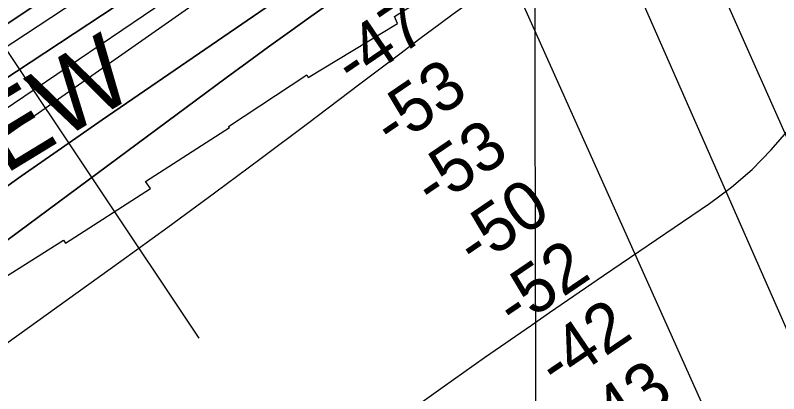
# Model space of a CAD drawing. Extents: x 3324104 to 3361979, y 612876 to 638273.
# Drawn here: x 3353821 to 3354870, y 621139 to 621658 of the extents above; entities that cross this region are included whole.
import ezdxf

# ---------------------------------------------------------------- set-up
doc = ezdxf.new("R2010")
doc.units = 0
for name, color, linetype in [('V-GRID-MAJR', 7, 'Continuous'), ('V-RIVR-EDGE', 7, 'Continuous'), ('V-RIVR-RANG', 7, 'Continuous'), ('V-RRAP-RVMT', 7, 'Continuous'), ('V-RRAP-RVMT-IDEN', 7, 'Continuous'), ('V-TOPO-DPTH', 7, 'Continuous'), ('V-TOPO-MAJR', 7, 'Continuous'), ('V-TOPO-MINR', 7, 'Continuous'), ('V-TOPO-WATR', 7, 'Continuous'), ('V-UTIL-LINE', 7, 'Continuous')]:
    doc.layers.add(name, color=color, linetype=linetype)

msp = doc.modelspace()

# ---------------------------------------------------------------- linework, layer by layer
at = {"layer": 'V-GRID-MAJR'}
msp.add_spline([(3354542.6, 618302.9), (3354530.3, 624362.2), (3354517.9, 630423.5), (3354505.6, 636484.8), (3354505.6, 636486.7)], degree=3, dxfattribs=at)
at = {"layer": 'V-RIVR-EDGE'}
msp.add_spline([(3356052, 622889.6), (3356029.2, 622881.4), (3356012.5, 622875.7), (3355994.6, 622867.2), (3355977.5, 622859.1), (3355958.5, 622851), (3355948.4, 622843.2), (3355934, 622834.7), (3355904.1, 622817.8), (3355878.1, 622802.3), (3355856.7, 622790.3), (3355830, 622776.4), (3355805.1, 622765.6), (3355764.7, 622744.8), (3355744.1, 622733.6), (3355694.1, 622710.9), (3355668.4, 622698.1), (3355641.6, 622685), (3355605.1, 622669.2), (3355569.4, 622657.3), (3355539.2, 622646.5), (3355510.8, 622636.8), (3355482.1, 622628.4), (3355461.9, 622623), (3355442.5, 622614.1), (3355422.7, 622607.2), (3355409.5, 622603.4), (3355389, 622597.6), (3355371.9, 622589.5), (3355349, 622581), (3355297.7, 622547), (3355260, 622525.8), (3355211.1, 622494.5), (3355190.1, 622484.5), (3355184.7, 622482.9), (3355179.3, 622477.9), (3355174.2, 622475.6), (3355160.6, 622471), (3355143.5, 622463.6), (3355133.1, 622457.1), (3355125.7, 622450.5), (3355113.2, 622443.9), (3355096.9, 622433.1), (3355081, 622426.9), (3355064.3, 622419.2), (3355057, 622418.9), (3355048.8, 622414.6), (3355041.8, 622406.9), (3355036.8, 622406.5), (3355031.3, 622405.7), (3355027.1, 622404.2), (3355017.3, 622396.1), (3355010.7, 622394.9), (3355001.4, 622388.4), (3354988.6, 622379.1), (3354972.3, 622369.4), (3354947.4, 622356.3), (3354937.7, 622351.7), (3354926.1, 622343.6), (3354903.2, 622326.6), (3354891.1, 622318.1), (3354883.3, 622307.2), (3354879.4, 622304.1), (3354875.2, 622302.6), (3354867.8, 622299.1), (3354853, 622288.3), (3354842.5, 622279), (3354826.6, 622267.4), (3354807.2, 622259.7), (3354793.2, 622255.5), (3354765.7, 622249.7), (3354748.6, 622245.5), (3354734.6, 622239.3), (3354712.1, 622227.4), (3354697.7, 622218.9), (3354685.3, 622210), (3354640.6, 622184.5), (3354622, 622176), (3354616.2, 622175.2), (3354603.4, 622167.5), (3354578.9, 622157.1), (3354554.5, 622147.5), (3354537.4, 622142.9), (3354530.8, 622137.8), (3354500.1, 622122.8), (3354463.6, 622102.3), (3354417.8, 622078.8), (3354386.3, 622060.6), (3354340.1, 622032.4), (3354321.1, 622021.2), (3354285, 621998.8), (3354257, 621982.2), (3354217, 621958.7), (3354194.1, 621942.8), (3354177, 621931.6), (3354157.6, 621922), (3354141.6, 621910.4), (3354135.4, 621904.2), (3354130.4, 621897.6), (3354120.7, 621891.1), (3354104, 621882.9), (3354075.6, 621856.6), (3354044.9, 621835.4), (3354013, 621812.2), (3353971.5, 621781.7), (3353947.8, 621763.5), (3353941.2, 621763.5), (3353935.4, 621762.8), (3353929.5, 621760.1), (3353924.9, 621756.6), (3353920.6, 621751.5), (3353917.1, 621742.6), (3353910.5, 621741.5), (3353904.7, 621738.4), (3353893.8, 621731.1), (3353879.8, 621721.4), (3353866.2, 621708.6), (3353854.9, 621697.4), (3353843.3, 621687.8), (3353839.8, 621688.5), (3353831.2, 621686.2), (3353823.1, 621681.2), (3353818, 621677.3), (3353800.9, 621666.1), (3353790.8, 621663.1), (3353781.9, 621654.9), (3353777.6, 621651.8), (3353776.1, 621648.8), (3353775.7, 621643.7), (3353772.2, 621641), (3353755.9, 621632.1), (3353735.7, 621622.1), (3353718.6, 621608.2), (3353704.2, 621600.5), (3353694.1, 621596.6), (3353683.6, 621592.4), (3353671.2, 621584.2), (3353642.1, 621563), (3353599, 621534), (3353578.4, 621522.4), (3353556.2, 621507.7), (3353547.7, 621502), (3353525.9, 621489.2), (3353513.1, 621481.1), (3353497.2, 621468.3), (3353477, 621450.9), (3353453.3, 621436.6), (3353435.8, 621424.7), (3353404.7, 621401.1), (3353378.3, 621380.2), (3353361.6, 621368.6), (3353339.5, 621355.1), (3353319.6, 621342.4), (3353299.5, 621330), (3353283.5, 621324.6), (3353273, 621317.6), (3353254.8, 621296), (3353236.9, 621275.5), (3353219.4, 621258.8), (3353195.7, 621241.4), (3353168.5, 621221.3), (3353137.8, 621201.6), (3353112.2, 621185), (3353065.6, 621151.8), (3353022, 621122.8), (3352993.3, 621100.4), (3352956, 621073.3), (3352907, 621037.8), (3352853.8, 620991.8), (3352787.8, 620942.3), (3352749.7, 620913.3), (3352736.9, 620900.9), (3352733.3, 620892.8), (3352728.7, 620886.6), (3352719, 620881.2), (3352691.8, 620864.6), (3352660.3, 620841.8), (3352640.5, 620828.3), (3352623.4, 620811.2), (3352605.1, 620792.3), (3352593.5, 620783), (3352582.6, 620778.8), (3352566.3, 620771.4), (3352548, 620764.5), (3352522.4, 620751), (3352494.5, 620735.5), (3352482.4, 620727), (3352479.3, 620723.2), (3352477, 620717.4), (3352470.7, 620711.9), (3352456, 620707.3), (3352443.2, 620700.4), (3352419.1, 620685.7), (3352392.3, 620669.1), (3352362.8, 620650.9), (3352339.1, 620634.3), (3352315.4, 620615.4), (3352284.7, 620590.6), (3352258.7, 620571.3), (3352228.7, 620550.1), (3352193.4, 620527.6), (3352156.9, 620504.9), (3352131.6, 620487.5), (3352094, 620462.4), (3352049.3, 620433), (3351990.2, 620391.3), (3351936.6, 620357.3), (3351851.5, 620293.9), (3351833.3, 620281.5), (3351817, 620273.8), (3351794.1, 620257.9), (3351767.7, 620241), (3351719.9, 620206.2), (3351680.6, 620177.6), (3351657.3, 620160.6), (3351637.1, 620145.9), (3351623.1, 620135.4), (3351603.3, 620124.2), (3351588.6, 620120), (3351567.2, 620109.6), (3351552.1, 620103.4), (3351538.1, 620096.5), (3351523.7, 620086.4), (3351510.9, 620076.4), (3351503.5, 620069.8), (3351495.3, 620057.4), (3351486, 620042.3), (3351479.4, 620032.6), (3351469.7, 620022.6), (3351448.3, 620006.3), (3351431.6, 619994.8), (3351404.8, 619973.9), (3351378, 619951.8), (3351358.9, 619936.4), (3351332.1, 619915.5), (3351306.1, 619892.3), (3351274.6, 619858.2), (3351238.8, 619826.9), (3351215.1, 619805.7), (3351171.6, 619767.8), (3351145.5, 619739.5), (3351124.6, 619722.1), (3351105.9, 619707.8), (3351089.6, 619697), (3351079.5, 619691.2), (3351074, 619683.5), (3351058.1, 619666.4), (3351043.3, 619655.2), (3351015.4, 619634), (3350999, 619623.1), (3350992.1, 619617.3), (3350979.2, 619606.1), (3350966, 619594.5), (3350951.2, 619582.2), (3350935.7, 619567.8), (3350923.3, 619555.1), (3350910, 619544.3), (3350888.3, 619528), (3350846.7, 619504.1), (3350821.5, 619490.2), (3350811.4, 619483.6), (3350806, 619480.5), (3350800.9, 619473.2), (3350797.4, 619473.2), (3350793.9, 619474.3), (3350788.9, 619473.6), (3350786.9, 619472), (3350785.4, 619467.4), (3350785.4, 619462.7), (3350779.5, 619456.2), (3350765.9, 619445.7), (3350746.1, 619428.7), (3350722.4, 619409), (3350716.2, 619407.1), (3350713.1, 619404), (3350711.1, 619397), (3350708.8, 619391.6), (3350704.5, 619391.6), (3350693.3, 619385.8), (3350686.7, 619379.6), (3350679.6, 619368.4), (3350661.4, 619354.5), (3350648.6, 619344.4), (3350645.5, 619344.8), (3350638.5, 619339.4), (3350623.3, 619330.5), (3350616.3, 619326.3), (3350602.3, 619317.4), (3350598.8, 619308.8), (3350582.9, 619299.2), (3350553.8, 619276), (3350526.2, 619255.5), (3350493.5, 619231.9), (3350474.9, 619219.6), (3350474.5, 619213.8), (3350470.2, 619207.2), (3350459, 619202.5), (3350446.1, 619194), (3350441.1, 619189.8), (3350438.8, 619186.3), (3350434.5, 619180.9), (3350414.7, 619167.8), (3350401.5, 619159.3), (3350384.8, 619146.9), (3350369.6, 619133.7), (3350356.4, 619125.2), (3350350.9, 619119), (3350347.4, 619109.4), (3350338.1, 619097.8), (3350324.9, 619083.8), (3350308.6, 619069.9), (3350300.4, 619062.6), (3350296.1, 619062.6), (3350291.5, 619062.2), (3350274.8, 619050.6), (3350258.4, 619037.5), (3350251.8, 619032.8), (3350244.1, 619029.3), (3350233.6, 619028.2), (3350227.4, 619024.3), (3350220.4, 619017), (3350213, 619007.3), (3350202.1, 618996.9), (3350193.6, 618989.5), (3350179.6, 618985.3), (3350173.8, 618980.7), (3350164.8, 618978), (3350162.1, 618975.3), (3350159.4, 618971.4), (3350154.3, 618963.6), (3350145.8, 618953.2), (3350126, 618938.1), (3350102.7, 618923), (3350094.5, 618918.4), (3350086.3, 618913), (3350075.1, 618901), (3350064.2, 618892.1), (3350039.3, 618873.6), (3350021.8, 618861.6), (3350002, 618848.8), (3349991.9, 618844.2), (3349964.4, 618826.4), (3349938.7, 618807.1), (3349915.4, 618792.8), (3349892.5, 618778.9), (3349868, 618761.9), (3349852.5, 618753), (3349842.8, 618750), (3349830.4, 618739.1), (3349804.3, 618720.2), (3349777.9, 618697.8), (3349751.9, 618677.7), (3349729.7, 618661.4), (3349703.7, 618642.9), (3349678.8, 618629.8), (3349648.9, 618612), (3349624.5, 618595), (3349592.6, 618575.7), (3349570.5, 618564.9), (3349549.5, 618548.6), (3349505.2, 618518.1), (3349479.2, 618499.9), (3349471.4, 618494.5), (3349459, 618487.6), (3349438.4, 618472.1), (3349412.4, 618452.4), (3349379.7, 618429.6), (3349350.2, 618410.3), (3349303.2, 618374.7), (3349277.6, 618357.7), (3349264, 618347.3), (3349241.4, 618330.7), (3349226.7, 618319.9), (3349207.2, 618306.3), (3349193.2, 618293.5)], degree=3, dxfattribs=at)
at = {"layer": 'V-RIVR-RANG'}
msp.add_line((3353551, 621996.5), (3354073.7, 621215.2), dxfattribs=at)
at = {"layer": 'V-RRAP-RVMT'}
for p, q in [((3354342.3, 621656.8), (3354456.2, 621728.6)), ((3354346.4, 621647), (3354342.3, 621656.8)), ((3354223.9, 621573.2), (3354346.4, 621647)), ((3354114.5, 621506), (3354222, 621576.7)), ((3354222, 621576.7), (3354223.9, 621573.2)), ((3354000.4, 621430.3), (3354115.7, 621504.3)), ((3354115.7, 621504.3), (3354114.5, 621506)), ((3353890.4, 621345.8), (3354007.2, 621420.9)), ((3354007.2, 621420.9), (3354000.4, 621430.3)), ((3353776, 621279.7), (3353887.7, 621349.6)), ((3353887.7, 621349.6), (3353890.4, 621345.8))]:
    msp.add_line(p, q, dxfattribs=at)
at = {"layer": 'V-TOPO-DPTH'}
for points in [[(3353707.6, 621578.6), (3354161.9, 621881.5), (3354164.4, 621883.1), (3354167, 621884.7), (3354184.4, 621895.2), (3354194.4, 621901.2), (3354204.4, 621907.1), (3354214.6, 621912.9), (3354224.7, 621918.6), (3354783.7, 622229.3), (3354796.8, 622236.6), (3354809.9, 622243.8), (3354823.1, 622251), (3354836.3, 622258.2), (3354942.2, 622315.9)], [(3353707.6, 621578.6), (3354161.9, 621881.5), (3354164.4, 621883.1), (3354167, 621884.7), (3354184.4, 621895.2), (3354194.4, 621901.2), (3354204.4, 621907.1), (3354214.6, 621912.9), (3354224.7, 621918.6), (3354783.7, 622229.3), (3354796.8, 622236.6), (3354809.9, 622243.8), (3354823.1, 622251), (3354836.3, 622258.2), (3354942.2, 622315.9)], [(3353803, 621568), (3353882.1, 621620.4), (3353961.4, 621672.4), (3354040.9, 621724.2), (3354168.8, 621807.4), (3354184.4, 621817.4), (3354200.1, 621827.4), (3354215.8, 621837.2), (3354231.6, 621846.9), (3354650.5, 622101.7), (3354680.5, 622119.7), (3354710.6, 622137.6), (3354740.8, 622155.3), (3354771.2, 622172.8), (3354801.6, 622190), (3354832.1, 622207.2), (3354862.7, 622224.2), (3354893.4, 622241)], [(3354893.4, 622241), (3354862.7, 622224.2), (3354832.1, 622207.2), (3354801.6, 622190), (3354771.2, 622172.8), (3354740.8, 622155.3), (3354710.6, 622137.6), (3354680.5, 622119.7), (3354650.5, 622101.7), (3354231.6, 621846.9), (3354215.8, 621837.2), (3354200.1, 621827.4), (3354184.4, 621817.4), (3354168.8, 621807.4), (3354040.9, 621724.2), (3353961.4, 621672.4), (3353882.1, 621620.4), (3353803, 621568)], [(3354870.9, 622148.4), (3354834.6, 622127.8), (3354798.2, 622107.3), (3354651.6, 622024.7), (3354581, 621984.7), (3354510.4, 621944.6), (3354440, 621904.3), (3354369.7, 621863.8), (3354270.4, 621806.4), (3354249.9, 621794.4), (3354229.4, 621782.1), (3354209.2, 621769.6), (3354189, 621756.9), (3354169, 621743.9), (3354149.1, 621730.8), (3354129.4, 621717.4), (3354109.8, 621703.9), (3353576.5, 621331.2)], [(3354870.9, 622148.4), (3354834.6, 622127.8), (3354798.2, 622107.3), (3354651.6, 622024.7), (3354581, 621984.7), (3354510.4, 621944.6), (3354440, 621904.3), (3354369.7, 621863.8), (3354270.4, 621806.4), (3354249.9, 621794.4), (3354229.4, 621782.1), (3354209.2, 621769.6), (3354189, 621756.9), (3354169, 621743.9), (3354149.1, 621730.8), (3354129.4, 621717.4), (3354109.8, 621703.9), (3353576.5, 621331.2)], [(3353773.9, 621398.4), (3353829.4, 621437.5), (3353885, 621476.2), (3353940.9, 621514.8), (3354240.5, 621720.2), (3354251.1, 621727.3), (3354261.8, 621734.3), (3354272.5, 621741.1), (3354283.4, 621747.8), (3354461.4, 621855.7), (3354533.2, 621898.9), (3354605.3, 621941.6), (3354677.8, 621983.8), (3354750.4, 622025.6), (3354869.7, 622093.5), (3354882.9, 622101)], [(3353773.9, 621398.4), (3353829.4, 621437.5), (3353885, 621476.2), (3353940.9, 621514.8), (3354240.5, 621720.2), (3354251.1, 621727.3), (3354261.8, 621734.3), (3354272.5, 621741.1), (3354283.4, 621747.8), (3354461.4, 621855.7), (3354533.2, 621898.9), (3354605.3, 621941.6), (3354677.8, 621983.8), (3354750.4, 622025.6), (3354869.7, 622093.5), (3354882.9, 622101)], [(3354892.2, 622059.5), (3354562, 621866.6), (3354515.6, 621839.2), (3354469.4, 621811.6), (3354423.4, 621783.5), (3354377.5, 621755.2), (3354347, 621736.2), (3354316.8, 621717), (3354286.7, 621697.4), (3354257, 621677.2), (3354227.5, 621656.7), (3354198.3, 621635.9), (3354169.2, 621615), (3354140.2, 621593.8), (3354111.3, 621572.5), (3353703.3, 621270.4)], [(3353703.3, 621270.4), (3354111.3, 621572.5), (3354140.2, 621593.8), (3354169.2, 621615), (3354198.3, 621635.9), (3354227.5, 621656.7), (3354257, 621677.2), (3354286.7, 621697.4), (3354316.8, 621717), (3354347, 621736.2), (3354377.5, 621755.2), (3354423.4, 621783.5), (3354469.4, 621811.6), (3354515.6, 621839.2), (3354562, 621866.6), (3354892.2, 622059.5)]]:
    msp.add_lwpolyline(points, dxfattribs=at)
at = {"layer": 'V-TOPO-MAJR'}
for points in [[(3354915.1, 621979.7), (3354573.7, 621763.5), (3354535.3, 621738.6), (3354497.4, 621713.2), (3354460.1, 621686.9), (3354423.1, 621660), (3354405.2, 621646.6), (3354377.5, 621626), (3354349.9, 621605.3), (3354322.3, 621584.5), (3354294.7, 621563.7), (3354222.9, 621509.4), (3354159.2, 621461.7), (3354095.3, 621414.2), (3354031.1, 621367.3), (3353966.6, 621320.7), (3353764.1, 621175.3)], [(3354353, 621108), (3354409.3, 621148.5), (3354466, 621188.5), (3354530.7, 621233.3), (3354555.5, 621250.4), (3354580.2, 621267.4), (3354605.1, 621284.4), (3354629.9, 621301.4), (3354775.4, 621400.1), (3354805.5, 621422.7), (3354834, 621446.9), (3354860.2, 621473.6), (3354884.8, 621502.1)]]:
    msp.add_lwpolyline(points, dxfattribs=at)
at = {"layer": 'V-TOPO-MINR'}
for points in [[(3354871.8, 622257), (3354829.5, 622234.1), (3354824.3, 622231.2), (3354819, 622228.3), (3354813.8, 622225.4), (3354808.5, 622222.4), (3354688.4, 622154.7), (3354623.2, 622117.7), (3354558.2, 622080.3), (3354493.5, 622042.5), (3354428.9, 622004.4), (3354243, 621893.6), (3354212.2, 621875.1), (3354181.6, 621856.4), (3354151.1, 621837.4), (3354120.7, 621818.2), (3354112.8, 621813.1), (3354078.5, 621791.2), (3354044.4, 621769.1), (3354010.3, 621747), (3353976.3, 621724.8), (3353607.3, 621482.6)], [(3354893.4, 622241), (3354862.7, 622224.2), (3354832.1, 622207.2), (3354801.6, 622190), (3354771.2, 622172.8), (3354740.8, 622155.3), (3354710.6, 622137.6), (3354680.5, 622119.7), (3354650.5, 622101.7), (3354231.6, 621846.9), (3354215.8, 621837.2), (3354200.1, 621827.4), (3354184.4, 621817.4), (3354168.8, 621807.4), (3354040.9, 621724.2), (3353961.4, 621672.4), (3353882.1, 621620.4), (3353803, 621568)], [(3354874.3, 622189), (3354852.3, 622176.6), (3354830.3, 622164.1), (3354808.3, 622151.7), (3354468.8, 621958.7), (3354425.8, 621933.9), (3354383.1, 621908.8), (3354340.7, 621883.2), (3354298.5, 621857.2), (3354223, 621810.1), (3354218.8, 621807.4), (3354214.5, 621804.7), (3354210.3, 621801.9), (3354206.2, 621799.2), (3353788.9, 621517)], [(3354870.9, 622148.4), (3354834.6, 622127.8), (3354798.2, 622107.3), (3354651.6, 622024.7), (3354581, 621984.7), (3354510.4, 621944.6), (3354440, 621904.3), (3354369.7, 621863.8), (3354270.4, 621806.4), (3354249.9, 621794.4), (3354229.4, 621782.1), (3354209.2, 621769.6), (3354189, 621756.9), (3354169, 621743.9), (3354149.1, 621730.8), (3354129.4, 621717.4), (3354109.8, 621703.9), (3353576.5, 621331.2)], [(3354882.9, 622101), (3354869.7, 622093.5), (3354750.4, 622025.6), (3354677.8, 621983.8), (3354605.3, 621941.6), (3354533.2, 621898.9), (3354461.4, 621855.7), (3354283.4, 621747.8), (3354272.5, 621741.1), (3354261.8, 621734.3), (3354251.1, 621727.3), (3354240.5, 621720.2), (3353940.9, 621514.8), (3353885, 621476.2), (3353829.4, 621437.5), (3353773.9, 621398.4)], [(3354892.2, 622059.5), (3354562, 621866.6), (3354515.6, 621839.2), (3354469.4, 621811.6), (3354423.4, 621783.5), (3354377.5, 621755.2), (3354347, 621736.2), (3354316.8, 621717), (3354286.7, 621697.4), (3354257, 621677.2), (3354227.5, 621656.7), (3354198.3, 621635.9), (3354169.2, 621615), (3354140.2, 621593.8), (3354111.3, 621572.5), (3353703.3, 621270.4)]]:
    msp.add_lwpolyline(points, dxfattribs=at)
at = {"layer": 'V-TOPO-WATR'}
msp.add_lwpolyline([(3354942.2, 622315.9), (3354836.3, 622258.2), (3354823.1, 622251), (3354809.9, 622243.8), (3354796.8, 622236.6), (3354783.7, 622229.3), (3354224.7, 621918.6), (3354214.6, 621912.9), (3354204.4, 621907.1), (3354194.4, 621901.2), (3354184.4, 621895.2), (3354167, 621884.7), (3354164.4, 621883.1), (3354161.9, 621881.5), (3353707.6, 621578.6)], dxfattribs=at)
at = {"layer": 'V-UTIL-LINE'}
for p, q in [((3354457.1, 622445), (3355984.9, 619007.5)), ((3354352.9, 622427.7), (3355880.7, 618955.4)), ((3354196.7, 622392.9), (3355776.5, 618868.6))]:
    msp.add_line(p, q, dxfattribs=at)

# ---------------------------------------------------------------- texts
at = {"layer": 'V-RIVR-RANG'}
for s, p in [('-47', (3354285.8, 621558.8)), ('-53', (3354339.6, 621474.5)), ('-53', (3354395.6, 621391.6)), ('-50', (3354453.5, 621310.1)), ('-52', (3354507.9, 621226.2)), ('-42', (3354565.7, 621144.5)), ('-43', (3354621.2, 621061.3))]:
    msp.add_text(s, height=67, rotation=34.1752, dxfattribs=at).set_placement(p)
at = {"layer": 'V-RRAP-RVMT-IDEN'}
msp.add_text('NEW', height=100, rotation=31.3369, dxfattribs=at).set_placement((3353724.7, 621389.1))

doc.saveas('drawing.dxf')
